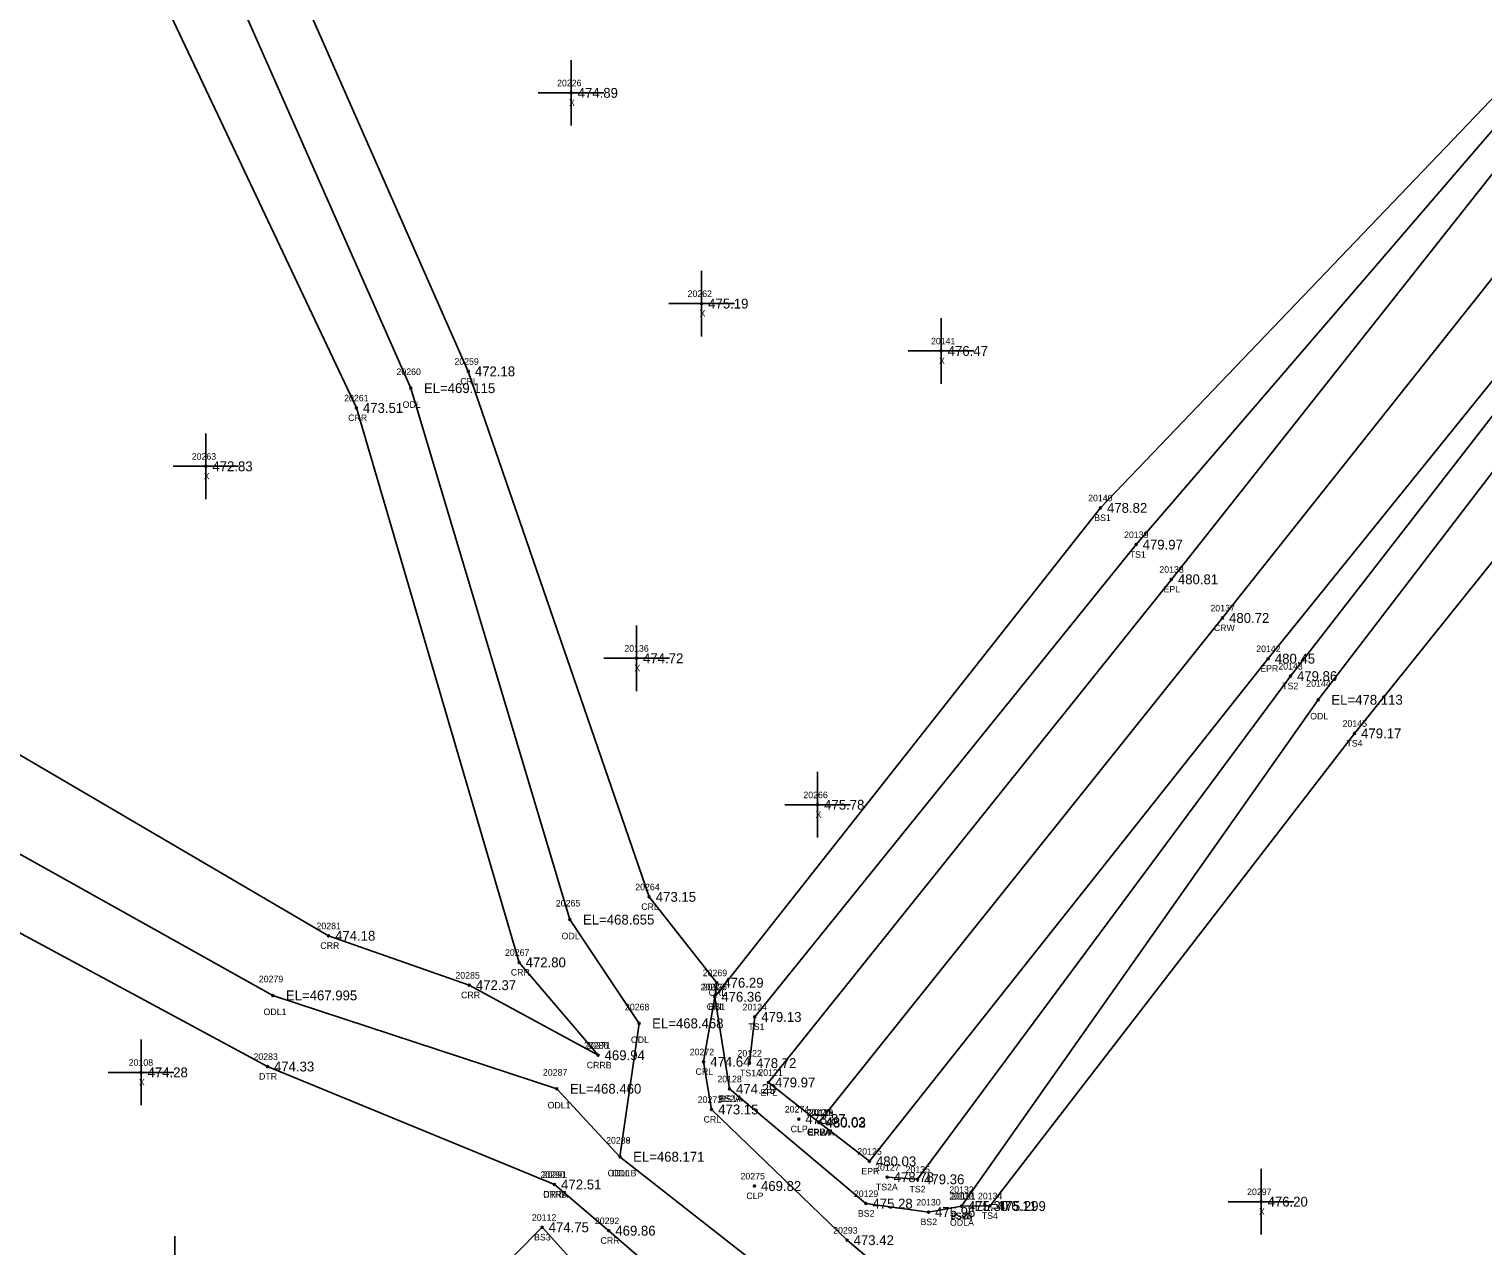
# Model space of a CAD drawing. Extents: x 1789565 to 1790548, y 909019 to 910194.
# Drawn here: x 1789950.9 to 1790172.5, y 909606.8 to 909792.3 of the extents above; entities that cross this region are included whole.
import ezdxf

# ---------------------------------------------------------------- set-up
doc = ezdxf.new("R2010")
doc.units = 0
for name, color, linetype in [('RD_DTM_BkLn1', 7, 'Continuous'), ('RD_DTM_BkLn2', 7, 'Continuous'), ('RD_DTM_BkLn_txCode', 7, 'Continuous'), ('RD_EX_H2O', 7, 'Continuous'), ('RD_EX_H2O_txCode', 7, 'Continuous'), ('RD_EX_Misc', 7, 'Continuous'), ('RD_EX_Misc_txCode', 7, 'Continuous'), ('RD_EX_Road', 7, 'Continuous'), ('RD_EX_Road_txCode', 7, 'Continuous'), ('RD_EX_TX_H2O_ELEV', 7, 'Continuous'), ('RD_EX_TX_Misc_ELEV', 7, 'Continuous'), ('RD_EX_TX_Road_ELEV', 7, 'Continuous'), ('RD_HC_Survey_ELEV', 7, 'Continuous'), ('RD_HC_Survey_txCode', 7, 'Continuous'), ('RD_SMD_Locator', 7, 'Continuous')]:
    doc.layers.add(name, color=color, linetype=linetype)

msp = doc.modelspace()

# ---------------------------------------------------------------- linework, layer by layer
at = {"layer": 'RD_DTM_BkLn1'}
msp.add_lwpolyline([(1790071.24, 909625.67), (1790132.78, 909702.56), (1790193.17, 909778.64), (1790254.11, 909855.13), (1790314.56, 909930.82), (1790375.87, 910006.79), (1790434.17, 910078.51), (1790495.95, 910153.23)], dxfattribs=at)
at = {"layer": 'RD_DTM_BkLn2'}
for points in [[(1790060.69, 909634.71), (1790061.47, 909641.75), (1790119.6, 909713.74), (1790183.37, 909787.88), (1790244.44, 909862.78), (1790306.19, 909938.82), (1790365.07, 910016.23), (1790422.97, 910088.22), (1790484.03, 910163.43)], [(1790081.67, 909617.32), (1790086.3, 909617), (1790143.13, 909693.7), (1790202.72, 909770.52), (1790263.97, 909846.87), (1790323.52, 909922.76), (1790384.66, 909999.25), (1790423.96, 910046.28)], [(1790092.97, 909612.92), (1790097.34, 909612.95), (1790152.91, 909684.97), (1790214.4, 909761.5), (1790270.76, 909842.42), (1790331.58, 909916.3), (1790391.85, 909993.49), (1790427.85, 910042.91), (1790426.19, 910046.57), (1790423.96, 910046.28)], [(1790057.63, 909630.78), (1790055.38, 909644.82), (1790114.17, 909719.34), (1790181.61, 909789.75)], [(1790057.63, 909630.78), (1790078.42, 909613.3), (1790087.97, 909612.01), (1790092.97, 909612.92)], [(1789838.38, 909362.25), (1789846.95, 909377.91), (1789909.75, 909460.83), (1789970.57, 909536.24), (1790016.56, 909597.04), (1790029.06, 909609.68), (1790034.63, 909603.55)]]:
    msp.add_lwpolyline(points, dxfattribs=at)
at = {"layer": 'RD_EX_H2O'}
for points in [[(1789916.44, 910152.62), (1789911.22, 910059.17), (1789911.57, 910015.4), (1789913.25, 909950.04), (1789954.03, 909857.92), (1789966.14, 909807.85), (1790000.75, 909734.57), (1790025.55, 909650.06), (1790037.59, 909635.91)], [(1789926.75, 910151.78), (1789921.87, 910061.22), (1789923.33, 910015.8), (1789922.65, 909953.15), (1789957.79, 909859.65), (1789976.3, 909811.78), (1790009.05, 909737.59), (1790033.3, 909656.58), (1790043.84, 909640.77), (1790040.94, 909620.44), (1790068.41, 909598.88), (1790105.46, 909552.21), (1790128.28, 909493.4), (1790125.72, 909445.59), (1790167.31, 909436.17), (1790202.14, 909447.88), (1790216.41, 909437.36), (1790196.97, 909382.86), (1790209.47, 909371.8), (1790248.65, 909379.51), (1790333.47, 909404.65), (1790412.72, 909370.84), (1790438.82, 909377.48), (1790480.23, 909327.32)], [(1789942.19, 910149.47), (1789928.94, 910061.47), (1789937.03, 910016.56), (1789929.09, 909954.8), (1789962.46, 909861.74), (1789984.97, 909814.65), (1790017.82, 909740.15), (1790045.4, 909660.05), (1790055.69, 909646.96), (1790055.38, 909644.82), (1790053.69, 909634.91), (1790054.91, 909627.64), (1790075.55, 909607.72), (1790122.18, 909568.31), (1790142.55, 909490.86), (1790145.56, 909467.27), (1790204.21, 909464.64), (1790228.21, 909444.34), (1790208.83, 909385.44), (1790245.53, 909398.45), (1790340.56, 909420.98), (1790422.56, 909390.06), (1790444.95, 909390.88), (1790496, 909329.5)], [(1790092.97, 909612.92), (1790147.38, 909690.09), (1790206.86, 909767.79), (1790266.43, 909845.39), (1790326.38, 909920.19), (1790387.41, 909997.35), (1790424.69, 910044.32)], [(1789927.47, 909694.53), (1789996.51, 909654.12), (1790017.97, 909646.59), (1790037.59, 909635.91)], [(1789918.17, 909684.03), (1789988.01, 909645.03), (1790031.31, 909630.8), (1790040.94, 909620.44)], [(1789916.77, 909672.15), (1789987.19, 909634.19), (1790030.97, 909616.21)], [(1790030.97, 909616.21), (1790039.23, 909609.17), (1790060.86, 909590.41), (1790089.09, 909540.87), (1790093.77, 909497), (1790113.81, 909430.51), (1790177.09, 909424.59), (1790197.54, 909430.06), (1790185.17, 909386.39), (1790196.62, 909365.47), (1790247.61, 909363.63), (1790324.38, 909372.65), (1790407.18, 909352.01), (1790424.72, 909347.04), (1790471.09, 909309.36)]]:
    msp.add_lwpolyline(points, dxfattribs=at)
at = {"layer": 'RD_EX_Misc'}
for p, q in [((1790033.49, 909777.6), (1790033.49, 909787.6)), ((1790028.49, 909782.6), (1790038.49, 909782.6)), ((1790053.38, 909745.48), (1790053.38, 909755.48)), ((1790048.38, 909750.48), (1790058.38, 909750.48)), ((1790089.89, 909738.26), (1790089.89, 909748.26)), ((1790084.89, 909743.26), (1790094.89, 909743.26)), ((1789977.81, 909720.68), (1789977.81, 909730.68)), ((1789972.81, 909725.68), (1789982.81, 909725.68)), ((1790043.46, 909691.42), (1790043.46, 909701.42)), ((1790038.46, 909696.42), (1790048.46, 909696.42)), ((1790071.06, 909669.09), (1790071.06, 909679.09)), ((1790066.06, 909674.09), (1790076.06, 909674.09)), ((1789967.93, 909628.3), (1789967.93, 909638.3)), ((1789962.93, 909633.3), (1789972.93, 909633.3)), ((1790138.65, 909608.59), (1790138.65, 909618.59)), ((1790133.65, 909613.59), (1790143.65, 909613.59)), ((1789973.09, 909598.33), (1789973.09, 909608.33))]:
    msp.add_line(p, q, dxfattribs=at)
at = {"layer": 'RD_EX_Road'}
for points in [[(1790071.29, 909625.64), (1790063.58, 909631.76), (1790124.98, 909708.45), (1790186, 909785.5), (1790246.28, 909861.1), (1790307.38, 909937.59), (1790368.26, 910012.93), (1790426.56, 910084.73), (1790488.45, 910159.81)], [(1790071.25, 909625.72), (1790078.96, 909619.74), (1790139.76, 909696.36), (1790200.89, 909772.13), (1790261.64, 909848.6), (1790322.1, 909924.01), (1790383.38, 910000.26), (1790441.69, 910072.01), (1790503.77, 910147.05)]]:
    msp.add_lwpolyline(points, dxfattribs=at)
at = {"layer": 'RD_SMD_Locator'}
for centre in [(1790033.49, 909782.6), (1790053.38, 909750.48), (1790089.89, 909743.26), (1790017.82, 909740.15), (1790009.05, 909737.59), (1790000.75, 909734.57), (1789977.81, 909725.68), (1790114.17, 909719.34), (1790119.6, 909713.74), (1790124.98, 909708.45), (1790132.78, 909702.56), (1790043.46, 909696.42), (1790139.76, 909696.36), (1790143.13, 909693.7), (1790147.38, 909690.09), (1790152.91, 909684.97), (1790071.06, 909674.09), (1790045.4, 909660.05), (1790033.3, 909656.58), (1789996.51, 909654.12), (1790025.55, 909650.06), (1790017.97, 909646.59), (1790055.69, 909646.96), (1789988.01, 909645.03), (1790055.38, 909644.82), (1790055.38, 909644.82), (1790061.47, 909641.75), (1790043.84, 909640.77), (1790037.59, 909635.91), (1790037.59, 909635.91), (1789967.93, 909633.3), (1789987.19, 909634.19), (1790053.69, 909634.91), (1790060.69, 909634.71), (1790031.31, 909630.8), (1790057.63, 909630.78), (1790057.63, 909630.78), (1790063.58, 909631.76), (1790054.91, 909627.64), (1790068.18, 909626.18), (1790071.24, 909625.67), (1790071.25, 909625.72), (1790071.29, 909625.64), (1790040.94, 909620.44), (1790040.94, 909620.44), (1790078.96, 909619.74), (1790030.97, 909616.21), (1790030.97, 909616.21), (1790061.43, 909615.98), (1790081.67, 909617.32), (1790086.3, 909617), (1790078.42, 909613.3), (1790097.34, 909612.95), (1790138.65, 909613.59), (1790087.97, 909612.01), (1790092.97, 909612.92), (1790092.97, 909612.92), (1790092.97, 909612.92), (1790029.06, 909609.68), (1790039.23, 909609.17), (1790075.55, 909607.72)]:
    msp.add_circle(centre, 0.15, dxfattribs=at)

# ---------------------------------------------------------------- texts
at = {"layer": 'RD_DTM_BkLn_txCode'}
for s, p in [('20140', (1790112.3, 909720.34)), ('BS1', (1790113.22, 909717.34)), ('20139', (1790117.77, 909714.74)), ('TS1', (1790118.64, 909711.74)), ('20143', (1790141.29, 909694.7)), ('TS2', (1790141.88, 909691.7)), ('20145', (1790151.08, 909685.97)), ('TS4', (1790151.67, 909682.97)), ('20126', (1790053.52, 909645.82)), ('BS1', (1790054.44, 909642.82)), ('20124', (1790059.63, 909642.75)), ('TS1', (1790060.51, 909639.75)), ('20122', (1790058.85, 909635.71)), ('TS1A', (1790059.24, 909632.71)), ('20123', (1790055.79, 909631.78)), ('20128', (1790055.79, 909631.78)), ('BS2A', (1790055.91, 909628.78)), ('BS1A', (1790056.2, 909628.78)), ('20127', (1790079.83, 909618.32)), ('20135', (1790084.47, 909618)), ('20129', (1790076.59, 909614.3)), ('TS2A', (1790079.94, 909615.32)), ('TS2', (1790085.06, 909615)), ('20130', (1790086.1, 909613.01)), ('20133', (1790091.14, 909613.92)), ('20131', (1790091.42, 909613.92)), ('20134', (1790095.5, 909613.95)), ('20112', (1790027.51, 909610.68)), ('BS2', (1790077.2, 909611.3)), ('BS2', (1790086.75, 909610.01)), ('TS4A', (1790091.24, 909610.92)), ('BS2B', (1790091.27, 909610.92)), ('TS4', (1790096.09, 909610.95)), ('BS3', (1790027.84, 909607.68))]:
    msp.add_text(s, height=1, dxfattribs=at).set_placement(p)
at = {"layer": 'RD_EX_H2O_txCode'}
for s, p in [('20259', (1790015.7, 909741.15)), ('20260', (1790006.87, 909739.59)), ('CRL', (1790016.59, 909738.15)), ('20261', (1789998.89, 909735.57)), ('ODL', (1790007.81, 909734.59)), ('CRR', (1789999.5, 909732.57)), ('20144', (1790145.55, 909692.09)), ('ODL', (1790146.14, 909687.09)), ('20264', (1790043.26, 909661.05)), ('20265', (1790031.16, 909658.58)), ('CRL', (1790044.18, 909658.05)), ('20281', (1789994.68, 909655.12)), ('CRR', (1789995.26, 909652.12)), ('ODL', (1790032.05, 909653.58)), ('20267', (1790023.41, 909651.06)), ('20285', (1790015.85, 909647.59)), ('CRR', (1790024.3, 909648.06)), ('20269', (1790053.55, 909647.96)), ('20279', (1789985.89, 909647.03)), ('20270', (1790053.22, 909645.82)), ('CRR', (1790016.72, 909644.59)), ('CRL', (1790054.46, 909644.96)), ('ODL1', (1789986.6, 909642.03)), ('20268', (1790041.7, 909642.77)), ('CRL', (1790054.15, 909642.82)), ('20286', (1790035.45, 909636.91)), ('20271', (1790035.76, 909636.91)), ('ODL', (1790042.6, 909637.77)), ('20283', (1789985.07, 909635.19)), ('20272', (1790051.57, 909635.91)), ('DTR', (1789985.92, 909632.19)), ('20287', (1790029.19, 909632.8)), ('CRRB', (1790035.87, 909633.91)), ('CRRB', (1790035.87, 909633.91)), ('CRL', (1790052.46, 909632.91)), ('ODL1', (1790029.9, 909627.8)), ('20273', (1790052.79, 909628.64)), ('CRL', (1790053.68, 909625.64)), ('20288', (1790038.82, 909622.44)), ('20289', (1790038.82, 909622.44)), ('20290', (1790028.81, 909617.21)), ('20291', (1790029.14, 909617.21)), ('ODL1B', (1790039.06, 909617.44)), ('ODL', (1790039.7, 909617.44)), ('20132', (1790091.14, 909614.92)), ('CRRA', (1790029.23, 909614.21)), ('DTRB', (1790029.23, 909614.21)), ('20292', (1790037.11, 909610.17)), ('ODLA', (1790091.24, 909609.92)), ('20293', (1790073.44, 909608.72)), ('CRR', (1790037.98, 909607.17))]:
    msp.add_text(s, height=1, dxfattribs=at).set_placement(p)
at = {"layer": 'RD_EX_Misc_txCode'}
for s, p in [('20226', (1790031.35, 909783.6)), ('X', (1790033.17, 909780.6)), ('20262', (1790051.24, 909751.48)), ('X', (1790053.06, 909748.48)), ('20141', (1790088.34, 909744.26)), ('X', (1790089.57, 909741.26)), ('20263', (1789975.66, 909726.68)), ('X', (1789977.49, 909723.68)), ('20136', (1790041.6, 909697.42)), ('X', (1790043.14, 909694.42)), ('20266', (1790068.89, 909675.09)), ('X', (1790070.75, 909672.09)), ('20108', (1789966.05, 909634.3)), ('X', (1789967.61, 909631.3)), ('20297', (1790136.53, 909614.59)), ('X', (1790138.33, 909611.59))]:
    msp.add_text(s, height=1, dxfattribs=at).set_placement(p)
at = {"layer": 'RD_EX_Road_txCode'}
for s, p in [('20138', (1790123.15, 909709.45)), ('EPL', (1790123.78, 909706.45)), ('20142', (1790137.92, 909697.36)), ('EPR', (1790138.53, 909694.36)), ('20121', (1790062.03, 909632.76)), ('EPL', (1790062.37, 909629.76)), ('20120', (1790069.38, 909626.72)), ('20119', (1790069.74, 909626.64)), ('EPRA', (1790069.53, 909623.72)), ('EPLA', (1790069.59, 909623.64)), ('20125', (1790077.12, 909620.74)), ('EPR', (1790077.73, 909617.74))]:
    msp.add_text(s, height=1, dxfattribs=at).set_placement(p)
at = {"layer": 'RD_EX_TX_H2O_ELEV'}
for s, p in [('472.18', (1790018.82, 909739.4)), ('EL=469.115', (1790011.05, 909736.84)), ('473.51', (1790001.75, 909733.82)), ('EL=478.113', (1790149.38, 909689.34)), ('473.15', (1790046.4, 909659.3)), ('EL=468.655', (1790035.3, 909655.83)), ('474.18', (1789997.51, 909653.37)), ('472.80', (1790026.55, 909649.31)), ('472.37', (1790018.97, 909645.84)), ('476.29', (1790056.69, 909646.21)), ('EL=467.995', (1789990.01, 909644.28)), ('476.36', (1790056.38, 909644.07)), ('EL=468.468', (1790045.84, 909640.02)), ('469.94', (1790038.59, 909635.16)), ('469.94', (1790038.59, 909635.16)), ('474.64', (1790054.69, 909634.16)), ('474.33', (1789988.19, 909633.44)), ('EL=468.460', (1790033.31, 909630.05)), ('473.15', (1790055.91, 909626.89)), ('EL=468.171', (1790042.94, 909619.69)), ('EL=468.171', (1790042.94, 909619.69)), ('472.51', (1790031.97, 909615.46)), ('472.51', (1790031.97, 909615.46)), ('EL=475.299', (1790094.97, 909612.17)), ('469.86', (1790040.23, 909608.42)), ('473.42', (1790076.55, 909606.97))]:
    msp.add_text(s, height=1.5, dxfattribs=at).set_placement(p)
at = {"layer": 'RD_EX_TX_Misc_ELEV'}
for s, p in [('474.89', (1790034.49, 909781.85)), ('475.19', (1790054.38, 909749.73)), ('476.47', (1790090.89, 909742.51)), ('472.83', (1789978.81, 909724.93)), ('478.82', (1790115.17, 909718.59)), ('479.97', (1790120.6, 909712.99)), ('474.72', (1790044.46, 909695.67)), ('479.86', (1790144.13, 909692.95)), ('479.17', (1790153.91, 909684.22)), ('475.78', (1790072.06, 909673.34)), ('476.36', (1790056.38, 909644.07)), ('479.13', (1790062.47, 909641)), ('478.72', (1790061.69, 909633.96)), ('474.28', (1789968.93, 909632.55)), ('474.29', (1790058.63, 909630.03)), ('474.29', (1790058.63, 909630.03)), ('478.78', (1790082.67, 909616.57)), ('479.36', (1790087.3, 909616.25)), ('475.28', (1790079.42, 909612.55)), ('475.30', (1790093.97, 909612.17)), ('475.30', (1790093.97, 909612.17)), ('476.11', (1790098.34, 909612.2)), ('476.20', (1790139.65, 909612.84)), ('475.96', (1790088.97, 909611.26)), ('474.75', (1790030.06, 909608.93))]:
    msp.add_text(s, height=1.5, dxfattribs=at).set_placement(p)
at = {"layer": 'RD_EX_TX_Road_ELEV'}
for s, p in [('480.81', (1790125.98, 909707.7)), ('480.45', (1790140.76, 909695.61)), ('479.97', (1790064.58, 909631.01)), ('480.03', (1790072.25, 909624.97)), ('480.03', (1790072.29, 909624.89)), ('480.03', (1790079.96, 909618.99))]:
    msp.add_text(s, height=1.5, dxfattribs=at).set_placement(p)
at = {"layer": 'RD_HC_Survey_ELEV'}
for s, p in [('480.72', (1790133.78, 909701.81)), ('473.87', (1790069.18, 909625.43)), ('480.02', (1790072.24, 909624.92)), ('469.82', (1790062.43, 909615.23))]:
    msp.add_text(s, height=1.5, dxfattribs=at).set_placement(p)
at = {"layer": 'RD_HC_Survey_txCode'}
for s, p in [('20137', (1790130.94, 909703.56)), ('CRW', (1790131.46, 909700.56)), ('20274', (1790066.06, 909627.18)), ('20118', (1790069.69, 909626.67)), ('CLP', (1790066.95, 909624.18)), ('CRWA', (1790069.44, 909623.67)), ('20275', (1790059.31, 909616.98)), ('CLP', (1790060.2, 909613.98))]:
    msp.add_text(s, height=1, dxfattribs=at).set_placement(p)

doc.saveas('drawing.dxf')
